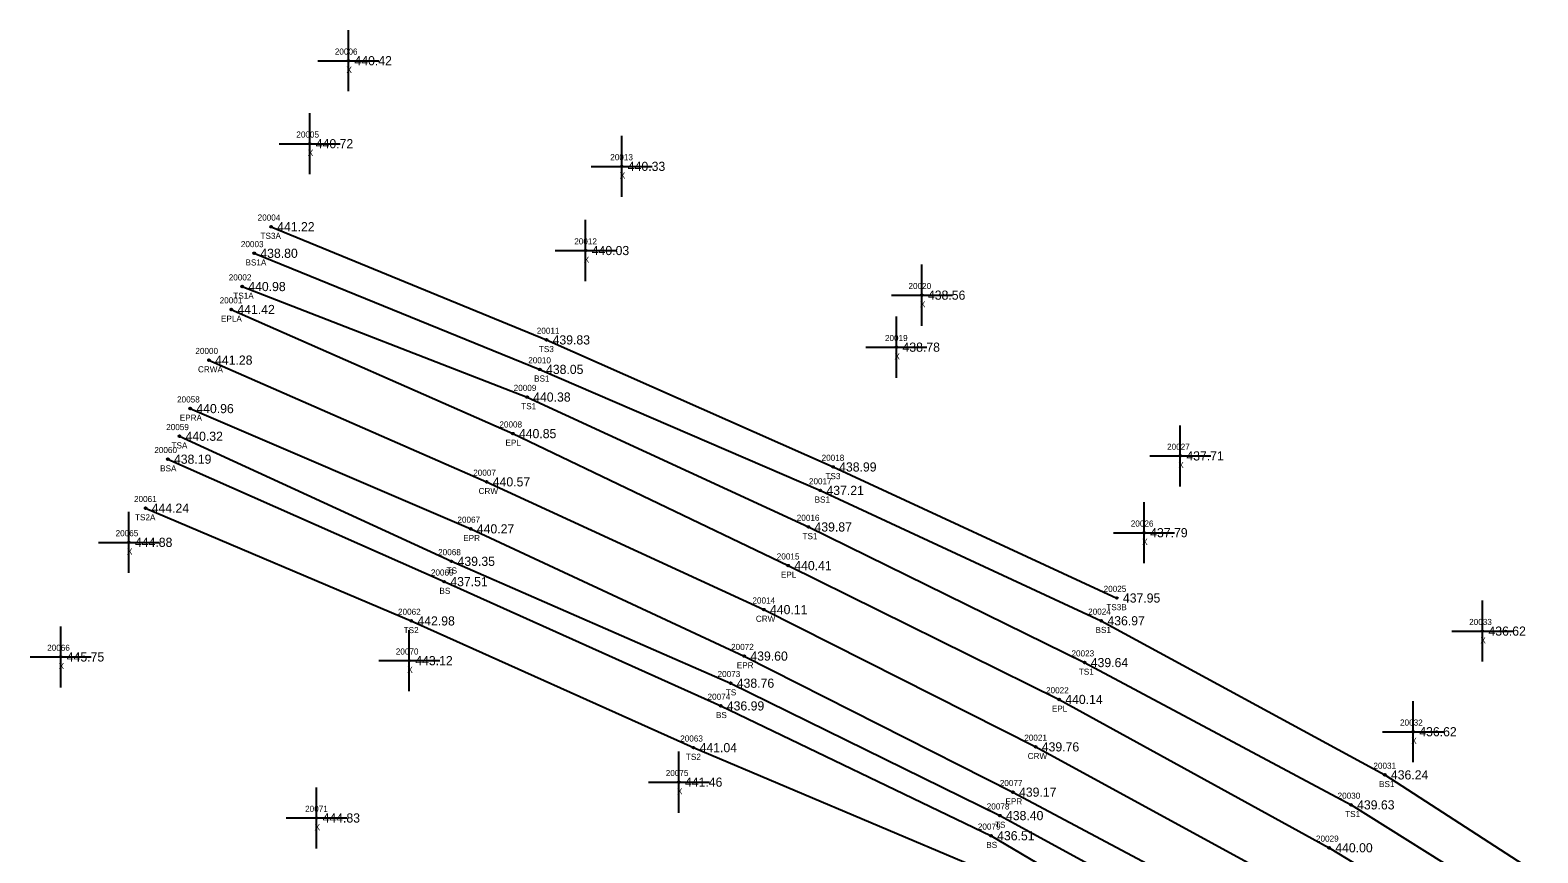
# Model space of a CAD drawing. Extents: x 1613836 to 1615109, y 777151 to 778248.
# Drawn here: x 1613835.9 to 1614083, y 778015.2 to 778149.9 of the extents above; entities that cross this region are included whole.
import ezdxf

# ---------------------------------------------------------------- set-up
doc = ezdxf.new("R2010")
doc.units = 0
for name, color, linetype in [('RD_DTM_BkLn1', 7, 'Continuous'), ('RD_DTM_BkLn2', 7, 'Continuous'), ('RD_DTM_BkLn_txCode', 7, 'Continuous'), ('RD_EX_Misc', 7, 'Continuous'), ('RD_EX_Misc_txCode', 7, 'Continuous'), ('RD_EX_Road', 7, 'Continuous'), ('RD_EX_Road_txCode', 7, 'Continuous'), ('RD_EX_TX_Misc_ELEV', 7, 'Continuous'), ('RD_EX_TX_Road_ELEV', 7, 'Continuous'), ('RD_HC_Survey_ELEV', 7, 'Continuous'), ('RD_HC_Survey_txCode', 7, 'Continuous'), ('RD_SMD_Locator', 7, 'Continuous')]:
    doc.layers.add(name, color=color, linetype=linetype)

msp = doc.modelspace()

# ---------------------------------------------------------------- linework, layer by layer
at = {"layer": 'RD_DTM_BkLn1'}
msp.add_lwpolyline([(1613865.21, 778095.86), (1613910.73, 778075.92), (1613956.18, 778054.99), (1614000.73, 778032.51), (1614044.52, 778008.68), (1614087.21, 777982.81), (1614129.12, 777955.82), (1614169.63, 777926.64), (1614209.9, 777896.76), (1614249.35, 777866.21), (1614288.43, 777835.55), (1614366.39, 777772.65), (1614443.98, 777709.72)], dxfattribs=at)
at = {"layer": 'RD_DTM_BkLn2'}
for points in [[(1613875.39, 778117.71), (1613920.54, 778099.17), (1613967.51, 778078.36), (1614014.03, 778056.89)], [(1613872.63, 778113.36), (1613919.46, 778094.34), (1613965.43, 778074.52), (1614011.49, 778053.16), (1614057.96, 778027.92), (1614098.58, 778001.66), (1614142.66, 777977.46), (1614185.05, 777949.4), (1614203.81, 777935.88)], [(1613870.65, 778107.91), (1613917.36, 778089.81), (1613963.47, 778068.53), (1614008.76, 778046.32), (1614052.42, 778023.01), (1614094.96, 777996.37), (1614137.71, 777969), (1614179.06, 777940.06), (1614196.49, 777927.41), (1614202.23, 777922.93), (1614210.94, 777920.91), (1614226.4, 777922.61), (1614267.62, 777889.85), (1614307.16, 777859.76), (1614381.32, 777790.21), (1614451.43, 777721.4), (1614453.49, 777722.08), (1614455.33, 777720.48), (1614437.07, 777696.16)], [(1613860.36, 778083.39), (1613904.96, 778062.9), (1613950.73, 778042.94), (1613994.86, 778021.25), (1614038.25, 777997.65), (1614118.58, 777941.84), (1614160.54, 777914.82), (1614182.29, 777896.21), (1614189.42, 777895.9), (1614196.65, 777882.72), (1614195.5, 777875.76), (1614231.56, 777844.86), (1614271.92, 777815.6), (1614305.89, 777789.49), (1614313.92, 777782.98), (1614351.2, 777751.93), (1614424.47, 777701.24), (1614433.25, 777695.63), (1614437.07, 777696.16)], [(1613858.47, 778079.63), (1613903.77, 778059.57), (1613949.1, 778039.22), (1613993.41, 778017.95), (1614036.6, 777992.42), (1614114.93, 777935.94), (1614154.39, 777905.9), (1614174.38, 777888.71)], [(1613854.82, 778071.61), (1613898.38, 778053.14), (1613944.64, 778032.38), (1613990.37, 778013.08), (1614032.71, 777987.43), (1614072.91, 777962.89), (1614114, 777931.46), (1614125.54, 777924.99)]]:
    msp.add_lwpolyline(points, dxfattribs=at)
at = {"layer": 'RD_EX_Misc'}
for p, q in [((1613888.06, 778139.9), (1613888.06, 778149.9)), ((1613883.06, 778144.9), (1613893.06, 778144.9)), ((1613881.72, 778126.31), (1613881.72, 778136.31)), ((1613932.87, 778122.6), (1613932.87, 778132.6)), ((1613876.72, 778131.31), (1613886.72, 778131.31)), ((1613927.87, 778127.6), (1613937.87, 778127.6)), ((1613926.96, 778108.81), (1613926.96, 778118.81)), ((1613921.96, 778113.81), (1613931.96, 778113.81)), ((1613982.07, 778101.5), (1613982.07, 778111.5)), ((1613977.07, 778106.5), (1613987.07, 778106.5)), ((1613977.9, 778092.98), (1613977.9, 778102.98)), ((1613972.9, 778097.98), (1613982.9, 778097.98)), ((1614024.43, 778075.17), (1614024.43, 778085.17)), ((1614019.43, 778080.17), (1614029.43, 778080.17)), ((1613852.08, 778061.01), (1613852.08, 778071.01)), ((1614018.5, 778062.59), (1614018.5, 778072.59)), ((1613847.08, 778066.01), (1613857.08, 778066.01)), ((1614013.5, 778067.59), (1614023.5, 778067.59)), ((1614073.95, 778046.47), (1614073.95, 778056.47)), ((1613840.9, 778042.24), (1613840.9, 778052.24)), ((1613898.03, 778041.63), (1613898.03, 778051.63)), ((1614068.95, 778051.47), (1614078.95, 778051.47)), ((1613835.9, 778047.24), (1613845.9, 778047.24)), ((1613893.03, 778046.63), (1613903.03, 778046.63)), ((1614062.61, 778029.99), (1614062.61, 778039.99)), ((1614057.61, 778034.99), (1614067.61, 778034.99)), ((1613942.24, 778021.73), (1613942.24, 778031.73)), ((1613937.24, 778026.73), (1613947.24, 778026.73)), ((1613882.84, 778015.86), (1613882.84, 778025.86)), ((1613877.84, 778020.86), (1613887.84, 778020.86))]:
    msp.add_line(p, q, dxfattribs=at)
at = {"layer": 'RD_EX_Road'}
for points in [[(1613868.87, 778104.15), (1613915.02, 778083.82), (1613960.16, 778062.2), (1614004.58, 778040.28), (1614048.84, 778015.98), (1614091.38, 777990.08), (1614134.36, 777962.6), (1614174.73, 777933.48), (1614192.07, 777920.58), (1614215.93, 777904.23), (1614254.59, 777873.05), (1614293.82, 777842.42), (1614371.74, 777779.59), (1614449.33, 777716.3), (1614443.98, 777709.72), (1614439.38, 777704.09)], [(1613862.14, 778087.92), (1613908.12, 778068.22), (1613952.96, 778047.38), (1613997, 778025.09), (1614041.16, 778001.63), (1614124.35, 777949.06), (1614164.51, 777920.91), (1614187.11, 777904.29), (1614205.27, 777889.82), (1614244.49, 777859.52), (1614283.42, 777829.45), (1614361.06, 777765.89), (1614439.38, 777704.09)]]:
    msp.add_lwpolyline(points, dxfattribs=at)
at = {"layer": 'RD_SMD_Locator'}
for centre in [(1613888.06, 778144.9), (1613881.72, 778131.31), (1613932.87, 778127.6), (1613875.39, 778117.71), (1613872.63, 778113.36), (1613926.96, 778113.81), (1613870.65, 778107.91), (1613982.07, 778106.5), (1613868.87, 778104.15), (1613920.54, 778099.17), (1613977.9, 778097.98), (1613865.21, 778095.86), (1613919.46, 778094.34), (1613862.14, 778087.92), (1613917.36, 778089.81), (1613860.36, 778083.39), (1613915.02, 778083.82), (1614024.43, 778080.17), (1613858.47, 778079.63), (1613967.51, 778078.36), (1613910.73, 778075.92), (1613965.43, 778074.52), (1613854.82, 778071.61), (1613908.12, 778068.22), (1613963.47, 778068.53), (1613852.08, 778066.01), (1614018.5, 778067.59), (1613904.96, 778062.9), (1613960.16, 778062.2), (1613903.77, 778059.57), (1614014.03, 778056.89), (1613898.38, 778053.14), (1613956.18, 778054.99), (1614011.49, 778053.16), (1614073.95, 778051.47), (1613840.9, 778047.24), (1613898.03, 778046.63), (1613952.96, 778047.38), (1614008.76, 778046.32), (1613950.73, 778042.94), (1613949.1, 778039.22), (1614004.58, 778040.28), (1614062.61, 778034.99), (1613944.64, 778032.38), (1614000.73, 778032.51), (1613942.24, 778026.73), (1614057.96, 778027.92), (1613997, 778025.09), (1613882.84, 778020.86), (1613994.86, 778021.25), (1614052.42, 778023.01), (1613993.41, 778017.95), (1614048.84, 778015.98)]:
    msp.add_circle(centre, 0.15, dxfattribs=at)

# ---------------------------------------------------------------- texts
at = {"layer": 'RD_DTM_BkLn_txCode'}
for s, p in [('20004', (1613873.19, 778118.71)), ('20003', (1613870.44, 778114.36)), ('TS3A', (1613873.66, 778115.71)), ('20002', (1613868.45, 778108.91)), ('BS1A', (1613871.2, 778111.36)), ('TS1A', (1613869.2, 778105.91)), ('20011', (1613918.95, 778100.17)), ('TS3', (1613919.29, 778097.17)), ('20010', (1613917.55, 778095.34)), ('BS1', (1613918.51, 778092.34)), ('20009', (1613915.16, 778090.81)), ('TS1', (1613916.4, 778087.81)), ('20059', (1613858.2, 778084.39)), ('20060', (1613856.25, 778080.63)), ('TSA', (1613859.07, 778081.39)), ('20018', (1613965.64, 778079.36)), ('BSA', (1613857.2, 778077.63)), ('20017', (1613963.56, 778075.52)), ('TS3', (1613966.27, 778076.36)), ('20061', (1613852.92, 778072.61)), ('BS1', (1613964.49, 778072.52)), ('TS2A', (1613853.09, 778069.61)), ('20016', (1613961.57, 778069.53)), ('TS1', (1613962.51, 778066.53)), ('20068', (1613902.78, 778063.9)), ('20069', (1613901.59, 778060.57)), ('TS', (1613904.17, 778060.9)), ('BS', (1613902.99, 778057.57)), ('20025', (1614011.87, 778057.89)), ('TS3B', (1614012.31, 778054.89)), ('20062', (1613896.2, 778054.14)), ('20024', (1614009.33, 778054.16)), ('TS2', (1613897.13, 778051.14)), ('BS1', (1614010.54, 778051.16)), ('20023', (1614006.6, 778047.32)), ('20073', (1613948.58, 778043.94)), ('TS1', (1614007.8, 778044.32)), ('20074', (1613946.94, 778040.22)), ('TS', (1613949.94, 778040.94)), ('BS', (1613948.32, 778037.22)), ('20063', (1613942.46, 778033.38)), ('TS2', (1613943.4, 778030.38)), ('20031', (1614056.09, 778028.92)), ('BS1', (1614057.02, 778025.92)), ('20030', (1614050.22, 778024.01)), ('20078', (1613992.71, 778022.25)), ('TS1', (1614051.46, 778021.01)), ('20079', (1613991.25, 778018.95)), ('TS', (1613994.07, 778019.25)), ('BS', (1613992.63, 778015.95))]:
    msp.add_text(s, height=1, dxfattribs=at).set_placement(p)
at = {"layer": 'RD_EX_Misc_txCode'}
for s, p in [('20006', (1613885.84, 778145.9)), ('X', (1613887.74, 778142.9)), ('20005', (1613879.53, 778132.31)), ('X', (1613881.41, 778129.31)), ('20013', (1613930.99, 778128.6)), ('X', (1613932.55, 778125.6)), ('20012', (1613925.09, 778114.81)), ('X', (1613926.65, 778111.81)), ('20020', (1613979.88, 778107.5)), ('X', (1613981.76, 778104.5)), ('20019', (1613976.02, 778098.98)), ('X', (1613977.58, 778095.98)), ('20027', (1614022.27, 778081.17)), ('X', (1614024.12, 778078.17)), ('20065', (1613849.9, 778067.01)), ('20026', (1614016.32, 778068.59)), ('X', (1614018.19, 778065.59)), ('X', (1613851.76, 778064.01)), ('20033', (1614071.79, 778052.47)), ('20066', (1613838.69, 778048.24)), ('20070', (1613895.84, 778047.63)), ('X', (1614073.63, 778049.47)), ('X', (1613840.58, 778045.24)), ('X', (1613897.72, 778044.63)), ('20032', (1614060.46, 778035.99)), ('X', (1614062.3, 778032.99)), ('20075', (1613940.09, 778027.73)), ('X', (1613941.93, 778024.73)), ('20071', (1613880.97, 778021.86)), ('X', (1613882.53, 778018.86))]:
    msp.add_text(s, height=1, dxfattribs=at).set_placement(p)
at = {"layer": 'RD_EX_Road_txCode'}
for s, p in [('20001', (1613866.96, 778105.15)), ('EPLA', (1613867.18, 778102.15)), ('20058', (1613859.98, 778088.92)), ('EPRA', (1613860.42, 778085.92)), ('20008', (1613912.82, 778084.82)), ('EPL', (1613913.81, 778081.82)), ('20067', (1613905.94, 778069.22)), ('EPR', (1613906.89, 778066.22)), ('20015', (1613958.29, 778063.2)), ('EPL', (1613958.96, 778060.2)), ('20072', (1613950.8, 778048.38)), ('EPR', (1613951.73, 778045.38)), ('20022', (1614002.43, 778041.28)), ('EPL', (1614003.38, 778038.28)), ('20077', (1613994.85, 778026.09)), ('EPR', (1613995.77, 778023.09)), ('20029', (1614046.68, 778016.98))]:
    msp.add_text(s, height=1, dxfattribs=at).set_placement(p)
at = {"layer": 'RD_EX_TX_Misc_ELEV'}
for s, p in [('440.42', (1613889.06, 778144.15)), ('440.72', (1613882.72, 778130.56)), ('440.33', (1613933.87, 778126.85)), ('441.22', (1613876.39, 778116.96)), ('438.80', (1613873.63, 778112.61)), ('440.03', (1613927.96, 778113.06)), ('440.98', (1613871.65, 778107.16)), ('438.56', (1613983.07, 778105.75)), ('439.83', (1613921.54, 778098.42)), ('438.78', (1613978.9, 778097.23)), ('438.05', (1613920.46, 778093.59)), ('440.38', (1613918.36, 778089.06)), ('440.32', (1613861.36, 778082.64)), ('438.19', (1613859.47, 778078.88)), ('437.71', (1614025.43, 778079.42)), ('438.99', (1613968.51, 778077.61)), ('437.21', (1613966.43, 778073.77)), ('444.24', (1613855.82, 778070.86)), ('439.87', (1613964.47, 778067.78)), ('437.79', (1614019.5, 778066.84)), ('444.88', (1613853.08, 778065.26)), ('439.35', (1613905.96, 778062.15)), ('437.51', (1613904.77, 778058.82)), ('437.95', (1614015.03, 778056.14)), ('442.98', (1613899.38, 778052.39)), ('436.97', (1614012.49, 778052.41)), ('436.62', (1614074.95, 778050.72)), ('445.75', (1613841.9, 778046.49)), ('443.12', (1613899.03, 778045.88)), ('439.64', (1614009.76, 778045.57)), ('438.76', (1613951.73, 778042.19)), ('436.99', (1613950.1, 778038.47)), ('436.62', (1614063.61, 778034.24)), ('441.04', (1613945.64, 778031.63)), ('436.24', (1614058.96, 778027.17)), ('441.46', (1613943.24, 778025.98)), ('439.63', (1614053.42, 778022.26)), ('444.83', (1613883.84, 778020.11)), ('438.40', (1613995.86, 778020.5)), ('436.51', (1613994.41, 778017.2))]:
    msp.add_text(s, height=1.5, dxfattribs=at).set_placement(p)
at = {"layer": 'RD_EX_TX_Road_ELEV'}
for s, p in [('441.42', (1613869.87, 778103.4)), ('440.96', (1613863.14, 778087.17)), ('440.85', (1613916.02, 778083.07)), ('440.27', (1613909.12, 778067.47)), ('440.41', (1613961.16, 778061.45)), ('439.60', (1613953.96, 778046.63)), ('440.14', (1614005.58, 778039.53)), ('439.17', (1613998, 778024.34)), ('440.00', (1614049.84, 778015.23))]:
    msp.add_text(s, height=1.5, dxfattribs=at).set_placement(p)
at = {"layer": 'RD_HC_Survey_ELEV'}
for s, p in [('441.28', (1613866.21, 778095.11)), ('440.57', (1613911.73, 778075.17)), ('440.11', (1613957.18, 778054.24)), ('439.76', (1614001.73, 778031.76))]:
    msp.add_text(s, height=1.5, dxfattribs=at).set_placement(p)
at = {"layer": 'RD_HC_Survey_txCode'}
for s, p in [('20000', (1613862.98, 778096.86)), ('CRWA', (1613863.41, 778093.86)), ('20007', (1613908.53, 778076.92)), ('CRW', (1613909.41, 778073.92)), ('20014', (1613954.3, 778055.99)), ('CRW', (1613954.86, 778052.99)), ('20021', (1613998.86, 778033.51)), ('CRW', (1613999.42, 778030.51))]:
    msp.add_text(s, height=1, dxfattribs=at).set_placement(p)

doc.saveas('drawing.dxf')
